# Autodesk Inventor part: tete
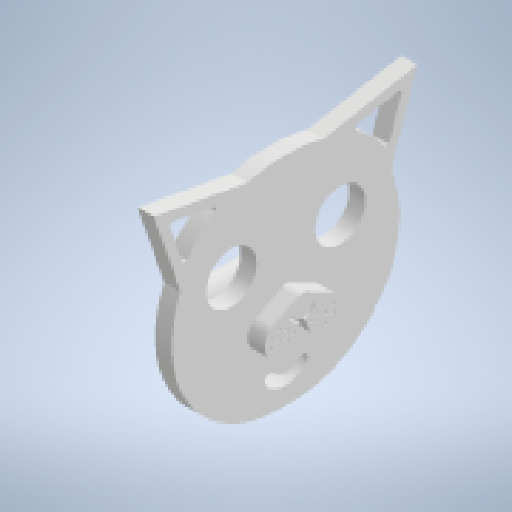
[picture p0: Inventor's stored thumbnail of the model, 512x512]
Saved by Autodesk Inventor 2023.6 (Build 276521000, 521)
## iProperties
Created: 2026-01
Part Number: tete
Material: Générique
Document SubType Name: Modeling
Designer: mel
Density: 1 g/cm^3
Appearance: Terre battue - Brun foncé
Author: mel
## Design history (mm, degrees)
sketch "Esquisse1"
  geometry: L1 (29.88, -11.963)-(31.792, -21.628); L2 (31.792, -21.628)-(23.414, -18.69); L3 (19.687, -19.385)-(34.119, -24.295); L4 (34.119, -24.295)-(30.925, -6.949); L5 (44.16, 0.05)-(-13.704, 0.05); L6 (29.88, 12.063)-(31.792, 21.728); L7 (31.792, 21.728)-(23.414, 18.79); L8 (19.687, 19.485)-(34.119, 24.395); L9 (34.119, 24.395)-(30.925, 7.049); C1 r 4.667 at (17.203, -10); C2 r 4.667 at (17.203, 10.1); A1 r 21.164 centre (11.764, -1.021) between (23.414, -18.69) and (29.88, -11.963); A2 r 21.164 centre (11.764, -1.021) between (23.414, -18.69) and (29.88, -11.963); A3 r 20 centre (11.764, -1.021) between (-8.208, 0.05) and (19.687, -19.385); A4 r 20.057 centre (11.764, -1.021) between (30.925, -6.949) and (31.792, 0.05); A5 r 21.164 centre (11.764, 1.121) between (29.88, 12.063) and (23.414, 18.79); A6 r 21.164 centre (11.764, 1.121) between (29.88, 12.063) and (23.414, 18.79); A7 r 20 centre (11.764, 1.121) between (19.687, 19.485) and (-8.208, 0.05); A8 r 20.057 centre (11.764, 1.121) between (31.792, 0.05) and (30.925, 7.049); 2 further points
  constraints: 18 end point, 16 point on circle, 10 centre point, 9 symmetric about line, 2 point on line, 1 horizontal, 5 other
  dimensions: "d3" = 10 vertical distance of C1.centre point (0, 0) (= d2); "d37" = 20 radius of A3; "d39" = 9.33333 diameter of C1 (= d38)
extrude "Extrusion1" new body sketch "Esquisse1" distance "d4" = 3; taper "d5" = 0 deg
sketch "Esquisse2"
  geometry: L1 (0.001, 6.471)-(-0.507, 6.765); L2 (0.001, 11.529)-(-5.41, 8.648); L3 (0.001, 11.529)-(5.41, 8.648); L4 (-1.192, 4.944)-(-0.507, 6.765); L5 (1.191, 4.947)-(0.51, 6.765); L6 (0.51, 6.765)-(0.001, 6.471); A1 r 3 centre (-4, 6) between (-5.41, 8.648) and (-1.192, 4.944); A2 r 3 centre (4, 6) between (1.191, 4.947) and (5.41, 8.648); 2 further points
  constraints: 12 end point, 4 point on circle, 4 tangent, 2 centre point
  dimensions: "d6" = 6 diameter of A1; "d7" = 6 diameter of A2 (= d6); "d8" = 4 horizontal distance of A1.centre point (0, 0); "d9" = 4 horizontal distance of A2.centre point (0, 0); "d10" = 6 vertical distance of A1.centre point (0, 0); "d11" = 6 vertical distance of A2.centre point (0, 0) (= d10); "d12" = 9 distance of point (0.001, 9) point (0, 0)
extrude "Extrusion2" join sketch "Esquisse2" distance "d13" = 3; taper "d14" = 0 deg
fillet "Congé1" dims "d15" = 2
fillet "Congé2" dims "d16" = 2
sketch "Esquisse3"
  geometry: L1 (0.001, -3.956)-(0.001, -5.601); C1 r 0.25 at (-5.684, 6.699); C2 r 0.25 at (-5.684, 5.166); C3 r 0.25 at (-2.843, 6.699); C4 r 0.25 at (-2.843, 5.166); C5 r 0.25 at (-4.354, 5.885); C6 r 0.25 at (-1.797, 5.885); C7 r 0.25 at (-4.354, 4.123); C8 r 0.25 at (-4.354, 7.503); C9 r 0.25 at (2.846, 6.699); C10 r 0.25 at (4.357, 7.503); C11 r 0.25 at (2.846, 5.166); C12 r 0.25 at (4.357, 5.885); C13 r 0.25 at (5.687, 6.699); C14 r 0.25 at (5.687, 5.166); C15 r 0.25 at (1.799, 5.885); C16 r 0.25 at (4.357, 4.123); A1 r 2 centre (0.001, 9.263) between (0.941, 11.028) and (-0.939, 11.028) reference; A2 r 2.282 centre (0.001, 9.263) between (-2.05, 8.263) and (2.052, 8.263); A3 r 2.564 centre (0.001, 9.263) between (-2.303, 8.139) and (2.306, 8.139); A4 r 2 centre (0.001, 9.263) between (-1.797, 8.386) and (1.799, 8.386); A5 r 0.282 centre (-2.05, 8.263) between (-1.797, 8.386) and (-2.303, 8.139); A6 r 0.282 centre (2.052, 8.263) between (2.306, 8.139) and (1.799, 8.386); A7 r 2 centre (0.001, 8.699) between (-0.507, 6.765) and (0.51, 6.765) reference; 1 further point
  constraints: 21 centre point, 10 point on circle, 8 symmetric about line, 5 tangent, 2 end point, 1 coincident, 1 vertical, 8 other
  dimensions: "d17" = 2 radius of A4; "d18" = 1 vertical distance of A2.centre A2.end; "d19" = 1 vertical distance of A2.centre A2.start (= d18); "d20" = 0.5 diameter of C1; "d21" = 0.5 diameter of C2; "d22" = 0.5 diameter of C3; "d23" = 0.5 diameter of C4; "d24" = 0.5 diameter of C5; "d25" = 0.5 diameter of C6; "d26" = 0.5 diameter of C7; "d27" = 0.5 diameter of C8
extrude "Extrusion3" cut sketch "Esquisse3" distance "d28" = 3; taper "d29" = 0 deg
sketch "Esquisse4"
  geometry: L1 (0, 6.444)-(-1.67, 6.444); L2 (-1.67, 1.444)-(0, 1.444); L3 (0, 1.444)-(0, 6.444); C1 r 2.5 at (-6, 3.944); A1 r 5 centre (-6, 3.944) between (-1.67, 6.444) and (-1.67, 1.444); 2 further points
  constraints: 6 end point, 2 centre point, 2 point on circle, 1 coincident, 1 horizontal, 1 parallel
  dimensions: "d30" = 10 diameter of A1; "d31" = 5 diameter of C1; "d35" = 7 vertical distance of A1.centre point (0, -3.056)
extrude "Extrusion4" join sketch "Esquisse4" stored distance "d32" = 19.5; taper "d33" = 0 deg
fillet "Congé3" dims "d40" = 0.5
sketch "Esquisse5"
  geometry: A1 r 4 centre (0, 0) between (-3.024, -2.618) and (3.07, -2.564); A2 r 5 centre (0, 0) between (-3.78, -3.273) and (3.837, -3.205); A3 r 3 centre (0, 0) between (-2.268, -1.964) and (2.302, -1.923); A4 r 1 centre (-3.024, -2.618) between (-2.268, -1.964) and (-3.78, -3.273); A5 r 1 centre (3.07, -2.564) between (3.837, -3.205) and (2.302, -1.923); 1 further point
  constraints: 10 point on circle, 5 centre point, 4 tangent, 1 coincident
  dimensions: "d41" = 3 radius of A3; "d42" = 5 radius of A2
extrude "Extrusion5" cut sketch "Esquisse5" extent not by distance; stored distance "d43" = 0; taper "d44" = 0 deg
node "Solide1"
other parameters: "d2" = 10, "d38" = 9.33333
